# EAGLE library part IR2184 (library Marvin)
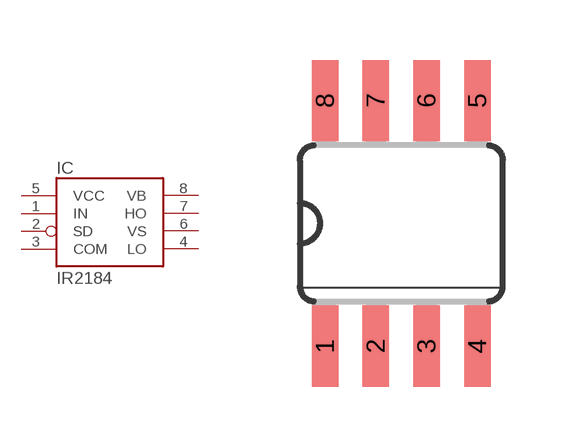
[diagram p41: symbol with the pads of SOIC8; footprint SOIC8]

Designator prefix IC

## IR2184S  [SOIC8]
1  IN
2  SD
3  COM
4  LO
5  VCC
6  VS
7  HO
8  VB

## Footprint SOIC8 (pad centres in mm)
smd 0.66 x 2.032: 1 -1.905,-3.073; 2 -0.635,-3.073; 3 0.635,-3.073; 4 1.905,-3.073; 5 1.905,3.073; 6 0.635,3.073; 7 -0.635,3.073; 8 -1.905,3.073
